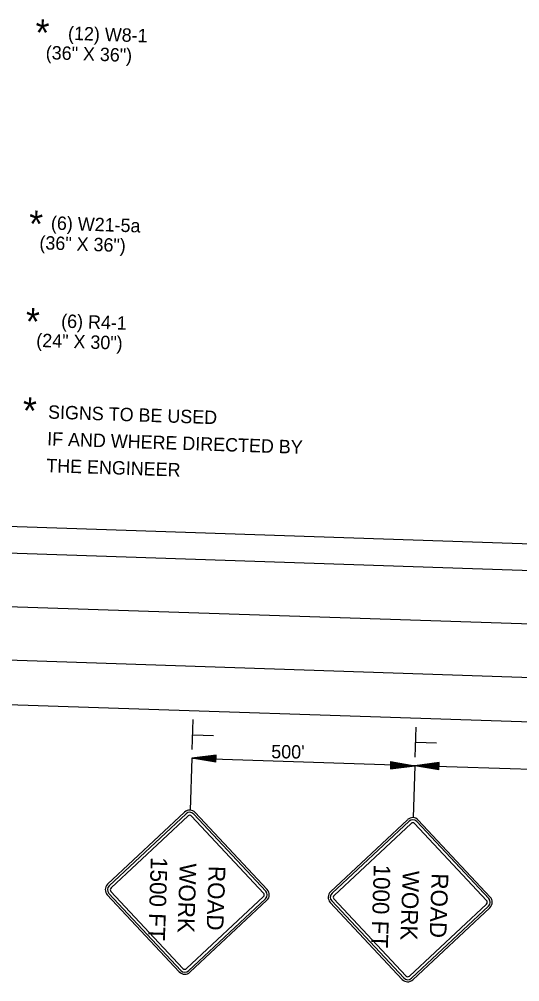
# Model space of a CAD drawing. Extents: x 977269 to 979191, y 1525946 to 1526973.
# Drawn here: x 977544 to 977768.3, y 1526503 to 1526934.3 of the extents above; entities that cross this region are included whole.
import ezdxf

# ---------------------------------------------------------------- set-up
doc = ezdxf.new("R2010")
doc.units = 0
for name, color, linetype in [('R_Border', 7, 'Continuous'), ('R_Border Prem', 7, 'Continuous'), ('STAMP', 7, 'Continuous'), ('STAMP_PP', 7, 'Continuous')]:
    doc.layers.add(name, color=color, linetype=linetype)

msp = doc.modelspace()

# ---------------------------------------------------------------- linework, layer by layer
at = {"layer": 'STAMP'}
for p, q in [((977460.97, 1526709.71), (977894.74, 1526695.24)), ((977460.57, 1526697.75), (977894.34, 1526683.28)), ((977459.77, 1526673.82), (977893.54, 1526659.36)), ((977458.97, 1526649.9), (977892.74, 1526635.43)), ((977458.31, 1526629.96), (977892.08, 1526615.49)), ((977621.43, 1526607.01), (977621.88, 1526620.46)), ((977721.38, 1526603.67), (977721.83, 1526617.13)), ((977621.85, 1526613.7), (977631.04, 1526613.39)), ((977721.79, 1526610.36), (977730.98, 1526610.06)), ((977621.3, 1526603.16), (977620.53, 1526579.87)), ((977632.21, 1526604.6), (977621.3, 1526603.16)), ((977632.15, 1526601.34), (977621.3, 1526603.16)), ((977721.25, 1526599.82), (977621.43, 1526603.12)), ((977632.21, 1526604.33), (977623.12, 1526603.13)), ((977632.16, 1526601.61), (977623.12, 1526603.13)), ((977632.2, 1526604.05), (977624.99, 1526603.09)), ((977632.16, 1526601.89), (977624.99, 1526603.09)), ((977632.2, 1526603.78), (977626.8, 1526603.06)), ((977632.17, 1526602.16), (977626.8, 1526603.06)), ((977632.19, 1526603.5), (977628.65, 1526603.03)), ((977632.17, 1526602.44), (977628.65, 1526603.03)), ((977632.19, 1526603.22), (977630.47, 1526603)), ((977632.18, 1526602.71), (977630.47, 1526603)), ((977632.15, 1526601.34), (977632.21, 1526604.6)), ((977710.4, 1526601.64), (977710.34, 1526598.38)), ((977710.34, 1526598.65), (977719.43, 1526599.85)), ((977710.34, 1526598.38), (977721.25, 1526599.82)), ((977710.35, 1526599.2), (977715.75, 1526599.92)), ((977710.35, 1526598.93), (977717.56, 1526599.89)), ((977710.36, 1526599.76), (977712.09, 1526599.98)), ((977710.36, 1526599.48), (977713.9, 1526599.95)), ((977710.38, 1526600.54), (977713.9, 1526599.95)), ((977710.38, 1526600.27), (977712.09, 1526599.98)), ((977710.39, 1526601.37), (977719.43, 1526599.85)), ((977710.39, 1526601.09), (977717.56, 1526599.89)), ((977710.39, 1526600.82), (977715.75, 1526599.92)), ((977710.4, 1526601.64), (977721.25, 1526599.82)), ((977721.25, 1526599.82), (977720.47, 1526576.54)), ((977732.16, 1526601.27), (977721.25, 1526599.82)), ((977821.19, 1526596.49), (977721.25, 1526599.82)), ((977732.1, 1526598.01), (977721.25, 1526599.82)), ((977732.15, 1526600.99), (977723.07, 1526599.79)), ((977732.1, 1526598.27), (977723.07, 1526599.79)), ((977732.15, 1526600.72), (977724.93, 1526599.76)), ((977732.11, 1526598.55), (977724.93, 1526599.76)), ((977732.14, 1526600.44), (977726.75, 1526599.73)), ((977732.11, 1526598.83), (977726.75, 1526599.73)), ((977732.14, 1526600.17), (977728.59, 1526599.7)), ((977732.12, 1526599.11), (977728.59, 1526599.7)), ((977732.13, 1526599.89), (977730.41, 1526599.67)), ((977732.13, 1526599.38), (977730.41, 1526599.67)), ((977732.1, 1526598.01), (977732.16, 1526601.27))]:
    msp.add_line(p, q, dxfattribs=at)
at = {"layer": 'STAMP_PP'}
for p, q in [((977583.6, 1526546.69), (977618.11, 1526578.96)), ((977584.24, 1526546), (977618.75, 1526578.28)), ((977585.14, 1526545.04), (977619.65, 1526577.32)), ((977621.24, 1526577.27), (977653.52, 1526542.76)), ((977622.19, 1526578.17), (977654.47, 1526543.66)), ((977622.88, 1526578.81), (977655.16, 1526544.3)), ((977683.55, 1526543.35), (977718.05, 1526575.63)), ((977684.19, 1526542.67), (977718.69, 1526574.95)), ((977685.09, 1526541.71), (977719.59, 1526573.99)), ((977721.18, 1526573.94), (977753.46, 1526539.43)), ((977722.14, 1526574.83), (977754.42, 1526540.33)), ((977722.82, 1526575.47), (977755.1, 1526540.97)), ((977616.41, 1526508.05), (977584.13, 1526542.56)), ((977617.37, 1526508.95), (977585.09, 1526543.45)), ((977615.72, 1526507.41), (977583.44, 1526541.92)), ((977653.46, 1526541.17), (977618.96, 1526508.89)), ((977654.36, 1526540.21), (977619.85, 1526507.94)), ((977655, 1526539.53), (977620.49, 1526507.25)), ((977715.67, 1526504.08), (977683.39, 1526538.58)), ((977716.35, 1526504.72), (977684.07, 1526539.22)), ((977717.31, 1526505.61), (977685.03, 1526540.12)), ((977753.41, 1526537.84), (977718.9, 1526505.56)), ((977754.3, 1526536.88), (977719.8, 1526504.6)), ((977754.94, 1526536.2), (977720.44, 1526503.92))]:
    msp.add_line(p, q, dxfattribs=at)
for centre, radius, start, end in [((977620.41, 1526576.5), 3.38, 43.0901, 133.0901), ((977620.41, 1526576.5), 2.44, 43.0901, 133.0901), ((977620.41, 1526576.5), 1.12, 43.0901, 133.0901), ((977720.36, 1526573.17), 3.38, 43.0901, 133.0901), ((977720.36, 1526573.17), 2.44, 43.0901, 133.0901), ((977720.36, 1526573.17), 1.12, 43.0901, 133.0901), ((977585.91, 1526544.22), 3.38, 133.0901, 223.0901), ((977585.91, 1526544.22), 2.44, 133.0901, 223.0901), ((977585.91, 1526544.22), 1.13, 133.0901, 223.0901), ((977652.69, 1526541.99), 1.13, 313.0901, 43.0901), ((977652.69, 1526541.99), 2.44, 313.0901, 43.0901), ((977652.69, 1526541.99), 3.38, 313.0901, 43.0901), ((977685.85, 1526540.89), 3.38, 133.0901, 223.0901), ((977685.85, 1526540.89), 2.44, 133.0901, 223.0901), ((977685.85, 1526540.89), 1.13, 133.0901, 223.0901), ((977752.64, 1526538.66), 1.13, 313.0901, 43.0901), ((977752.64, 1526538.66), 2.44, 313.0901, 43.0901), ((977752.64, 1526538.66), 3.38, 313.0901, 43.0901), ((977618.19, 1526509.72), 2.44, 223.0901, 313.0901), ((977618.19, 1526509.72), 1.12, 223.0901, 313.0901), ((977618.19, 1526509.72), 3.38, 223.0901, 313.0901), ((977718.13, 1526506.38), 3.38, 223.0901, 313.0901), ((977718.13, 1526506.38), 2.44, 223.0901, 313.0901), ((977718.13, 1526506.38), 1.12, 223.0901, 313.0901)]:
    msp.add_arc(centre, radius, start, end, dxfattribs=at)

# ---------------------------------------------------------------- texts
at = {"layer": 'R_Border'}
for s, p in [('(12) W8-1', (977565.76, 1526925.1)), ('(36" X 36")', (977555.78, 1526916.43)), ('(6) W21-5a', (977558.11, 1526840.07)), ('(36" X 36")', (977552.94, 1526831.23)), ('(6) R4-1', (977562.69, 1526796.13)), ('(24" X 30")', (977551.53, 1526787.5))]:
    msp.add_text(s, height=6, rotation=358.0901, dxfattribs=at).set_placement(p)
at = {"layer": 'R_Border Prem'}
for p in [(977551, 1526922.4), (977548.14, 1526836.71), (977546.68, 1526792.97), (977545.35, 1526753.02)]:
    msp.add_text('*', height=12, rotation=358.0901, dxfattribs=at).set_placement(p)
at = {"layer": 'STAMP'}
for s, rotation, p in [('SIGNS TO BE USED', 358.0901, (977556.82, 1526755.37)), ('IF AND WHERE DIRECTED BY', 358.0901, (977556.42, 1526743.37)), ('THE ENGINEER', 358.0901, (977556.02, 1526731.38)), ("500'", 359.3204, (977656.91, 1526603.16))]:
    msp.add_text(s, height=6, rotation=rotation, dxfattribs=at).set_placement(p)
at = {"layer": 'STAMP_PP'}
for s, p in [('1500 FT', (977602.99, 1526558.95)), ('WORK', (977615.93, 1526556.22)), (' ROAD ', (977629.01, 1526557.81)), ('1000 FT', (977702.93, 1526555.62)), ('WORK', (977715.87, 1526552.88)), (' ROAD ', (977728.95, 1526554.48))]:
    msp.add_text(s, height=7.5, rotation=268.0901, dxfattribs=at).set_placement(p)

doc.saveas('drawing.dxf')
